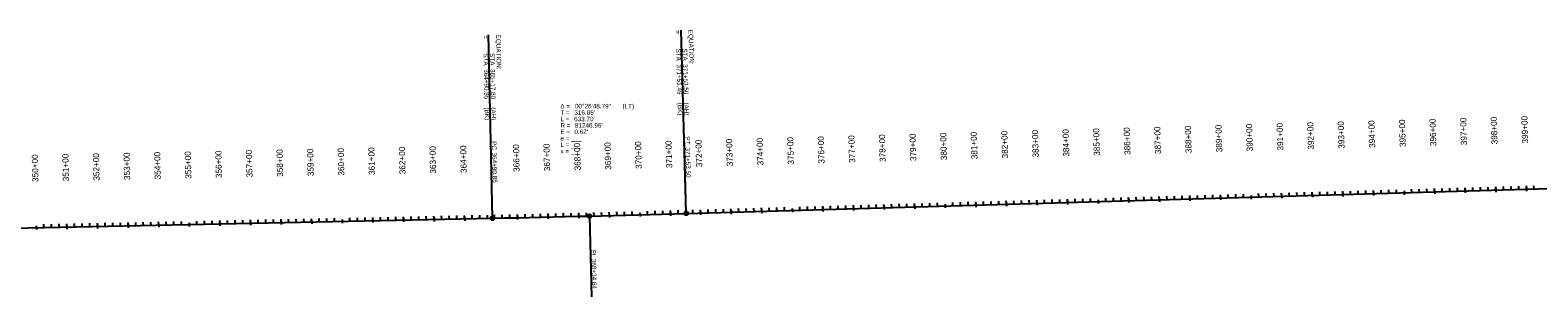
# Model space of a CAD drawing. Extents: x 22693007 to 22771804, y 6223023 to 6251673.
# Drawn here: x 22712700 to 22717627, y 6235361 to 6236234 of the extents above; entities that cross this region are included whole.
import ezdxf

# ---------------------------------------------------------------- set-up
doc = ezdxf.new("R2010")
doc.units = 0
for name, color, linetype in [('Default', 7, 'Continuous'), ('Draft_2', 7, 'Continuous'), ('NamedBoundary', 7, 'Continuous'), ('SheetBorder', 7, 'Continuous'), ('TextAlignment', 7, 'Continuous')]:
    doc.layers.add(name, color=color, linetype=linetype)

msp = doc.modelspace()

# ---------------------------------------------------------------- linework, layer by layer
at = {"layer": 'Default'}
for p, q in [((22714843.8, 6235633.8), (22719408.5, 6235765)), ((22714843.8, 6235633.8), (22719408.5, 6235765)), ((22709036.9, 6235509.8), (22714210.3, 6235618))]:
    msp.add_line(p, q, dxfattribs=at)
msp.add_arc((22712508.9, 6316847.2), 81247, 271.19995, 271.646835, dxfattribs=at)
at = {"layer": 'Draft_2'}
for p, q in [((22716789.5, 6235689.7), (22716789.2, 6235700.6)), ((22716889.5, 6235692.6), (22716889.2, 6235703.5)), ((22716989.4, 6235695.4), (22716989.1, 6235706.4)), ((22717089.4, 6235698.3), (22717089.1, 6235709.2)), ((22717189.2, 6235707.3), (22717189.5, 6235695.1)), ((22717289.3, 6235704.1), (22717289, 6235715)), ((22717389.3, 6235706.9), (22717389, 6235717.9)), ((22717489.2, 6235709.8), (22717488.9, 6235720.7)), ((22717589.2, 6235712.7), (22717588.9, 6235723.6)), ((22714990.3, 6235638), (22714989.9, 6235648.9)), ((22715090.2, 6235640.8), (22715089.9, 6235651.8)), ((22715190, 6235649.8), (22715190.4, 6235637.6)), ((22715290.1, 6235646.6), (22715289.8, 6235657.5)), ((22715390.1, 6235649.5), (22715389.8, 6235660.4)), ((22715490.1, 6235652.3), (22715489.7, 6235663.3)), ((22715590, 6235655.2), (22715589.7, 6235666.1)), ((22715689.8, 6235664.2), (22715690.1, 6235652)), ((22715789.9, 6235661), (22715789.6, 6235671.9)), ((22715889.9, 6235663.8), (22715889.6, 6235674.8)), ((22715989.9, 6235666.7), (22715989.5, 6235677.6)), ((22716089.8, 6235669.6), (22716089.5, 6235680.5)), ((22716189.6, 6235678.6), (22716189.9, 6235666.3)), ((22716289.7, 6235675.3), (22716289.4, 6235686.2)), ((22716389.7, 6235678.2), (22716389.4, 6235689.1)), ((22716489.6, 6235681.1), (22716489.3, 6235692)), ((22716589.6, 6235684), (22716589.3, 6235694.9)), ((22716689.4, 6235692.9), (22716689.7, 6235680.7)), ((22712819.8, 6235588.9), (22712819.6, 6235599.8)), ((22712919.8, 6235591), (22712919.5, 6235601.9)), ((22713019.7, 6235593.1), (22713019.5, 6235604)), ((22713119.7, 6235595.2), (22713119.5, 6235606.1)), ((22713219.6, 6235603.4), (22713219.8, 6235591.2)), ((22713319.7, 6235599.4), (22713319.4, 6235610.3)), ((22713419.7, 6235601.5), (22713419.4, 6235612.4)), ((22713519.6, 6235603.6), (22713519.4, 6235614.5)), ((22713619.6, 6235605.7), (22713619.4, 6235616.6)), ((22713719.5, 6235613.9), (22713719.7, 6235601.6)), ((22713819.6, 6235609.8), (22713819.3, 6235620.8)), ((22713919.5, 6235611.9), (22713919.3, 6235622.9)), ((22714019.5, 6235614), (22714019.3, 6235624.9)), ((22714119.5, 6235616.1), (22714119.3, 6235627)), ((22714292.5, 6235619.8), (22714292.3, 6235630.7)), ((22714392.5, 6235622), (22714392.2, 6235633)), ((22714492.5, 6235624.4), (22714492.2, 6235635.3)), ((22714592.4, 6235626.9), (22714592.1, 6235637.8)), ((22714692.2, 6235635.7), (22714692.6, 6235623.4)), ((22714792.4, 6235632.3), (22714792, 6235643.2)), ((22714890.3, 6235635.1), (22714890, 6235646)), ((22712719.7, 6235593), (22712719.9, 6235580.7))]:
    msp.add_line(p, q, dxfattribs=at)
at = {"layer": 'NamedBoundary'}
for p, q in [((22714843.8, 6235633.8), (22719408.5, 6235765)), ((22709036.9, 6235509.8), (22714210.3, 6235618))]:
    msp.add_line(p, q, dxfattribs=at)
msp.add_arc((22712508.9, 6316847.2), 81247, 271.19995, 271.646835, dxfattribs=at)
at = {"layer": 'SheetBorder'}
for p, q in [((22716714.6, 6235687.5), (22716714.2, 6235698.5)), ((22716739.5, 6235688.3), (22716739.2, 6235699.2)), ((22716764.5, 6235689), (22716764.2, 6235699.9)), ((22716814.5, 6235690.4), (22716814.2, 6235701.3)), ((22716839.5, 6235691.1), (22716839.2, 6235702.1)), ((22716864.5, 6235691.9), (22716864.2, 6235702.8)), ((22716889.3, 6235698.7), (22716889.7, 6235686.5)), ((22716914.5, 6235693.3), (22716914.2, 6235704.2)), ((22716939.5, 6235694), (22716939.1, 6235704.9)), ((22716964.4, 6235694.7), (22716964.1, 6235705.6)), ((22716989.3, 6235701.6), (22716989.6, 6235689.3)), ((22717014.4, 6235696.2), (22717014.1, 6235707.1)), ((22717039.4, 6235696.9), (22717039.1, 6235707.8)), ((22717064.4, 6235697.6), (22717064.1, 6235708.5)), ((22717089.2, 6235704.4), (22717089.6, 6235692.2)), ((22717114.4, 6235699), (22717114.1, 6235710)), ((22717139.4, 6235699.8), (22717139.1, 6235710.7)), ((22717164.4, 6235700.5), (22717164.1, 6235711.4)), ((22717189.2, 6235707.3), (22717189.5, 6235695.1)), ((22717214.3, 6235701.9), (22717214, 6235712.8)), ((22717239.3, 6235702.6), (22717239, 6235713.5)), ((22717264.3, 6235703.4), (22717264, 6235714.3)), ((22717289.1, 6235710.2), (22717289.5, 6235698)), ((22717314.3, 6235704.8), (22717314, 6235715.7)), ((22717339.3, 6235705.5), (22717339, 6235716.4)), ((22717364.3, 6235706.2), (22717364, 6235717.1)), ((22717389.1, 6235713.1), (22717389.4, 6235700.8)), ((22717414.3, 6235707.7), (22717413.9, 6235718.6)), ((22717439.3, 6235708.4), (22717438.9, 6235719.3)), ((22717464.2, 6235709.1), (22717463.9, 6235720)), ((22717489.1, 6235715.9), (22717489.4, 6235703.7)), ((22717514.2, 6235710.5), (22717513.9, 6235721.5)), ((22717539.2, 6235711.3), (22717538.9, 6235722.2)), ((22717564.2, 6235712), (22717563.9, 6235722.9)), ((22717589, 6235718.8), (22717589.4, 6235706.6)), ((22717614.2, 6235713.4), (22717613.9, 6235724.3)), ((22714965.3, 6235637.3), (22714965, 6235648.2)), ((22715015.3, 6235638.7), (22715014.9, 6235649.6)), ((22715040.2, 6235639.4), (22715039.9, 6235650.3)), ((22715065.2, 6235640.1), (22715064.9, 6235651)), ((22715115.2, 6235641.6), (22715114.9, 6235652.5)), ((22715140.2, 6235642.3), (22715139.9, 6235653.2)), ((22715165.2, 6235643), (22715164.9, 6235653.9)), ((22715190, 6235649.8), (22715190.4, 6235637.6)), ((22715215.2, 6235644.4), (22715214.9, 6235655.4)), ((22715240.2, 6235645.2), (22715239.8, 6235656.1)), ((22715265.1, 6235645.9), (22715264.8, 6235656.8)), ((22715290, 6235652.7), (22715290.3, 6235640.5)), ((22715315.1, 6235647.3), (22715314.8, 6235658.2)), ((22715340.1, 6235648), (22715339.8, 6235658.9)), ((22715365.1, 6235648.7), (22715364.8, 6235659.7)), ((22715389.9, 6235655.6), (22715390.3, 6235643.3)), ((22715415.1, 6235650.2), (22715414.8, 6235661.1)), ((22715440.1, 6235650.9), (22715439.8, 6235661.8)), ((22715465.1, 6235651.6), (22715464.8, 6235662.5)), ((22715489.9, 6235658.5), (22715490.2, 6235646.2)), ((22715515, 6235653.1), (22715514.7, 6235664)), ((22715540, 6235653.8), (22715539.7, 6235664.7)), ((22715565, 6235654.5), (22715564.7, 6235665.4)), ((22715589.8, 6235661.3), (22715590.2, 6235649.1)), ((22715615, 6235655.9), (22715614.7, 6235666.8)), ((22715640, 6235656.7), (22715639.7, 6235667.6)), ((22715665, 6235657.4), (22715664.7, 6235668.3)), ((22715689.8, 6235664.2), (22715690.1, 6235652)), ((22715715, 6235658.8), (22715714.6, 6235669.7)), ((22715740, 6235659.5), (22715739.6, 6235670.4)), ((22715764.9, 6235660.2), (22715764.6, 6235671.2)), ((22715789.8, 6235667.1), (22715790.1, 6235654.8)), ((22715814.9, 6235661.7), (22715814.6, 6235672.6)), ((22715839.9, 6235662.4), (22715839.6, 6235673.3)), ((22715864.9, 6235663.1), (22715864.6, 6235674)), ((22715889.7, 6235670), (22715890.1, 6235657.7)), ((22715914.9, 6235664.6), (22715914.6, 6235675.5)), ((22715939.9, 6235665.3), (22715939.6, 6235676.2)), ((22715964.9, 6235666), (22715964.5, 6235676.9)), ((22715989.7, 6235672.8), (22715990, 6235660.6)), ((22716014.8, 6235667.4), (22716014.5, 6235678.3)), ((22716039.8, 6235668.1), (22716039.5, 6235679.1)), ((22716064.8, 6235668.9), (22716064.5, 6235679.8)), ((22716089.6, 6235675.7), (22716090, 6235663.5)), ((22716114.8, 6235670.3), (22716114.5, 6235681.2)), ((22716139.8, 6235671), (22716139.5, 6235681.9)), ((22716164.8, 6235671.7), (22716164.5, 6235682.7)), ((22716189.6, 6235678.6), (22716189.9, 6235666.3)), ((22716214.8, 6235673.2), (22716214.4, 6235684.1)), ((22716239.7, 6235673.9), (22716239.4, 6235684.8)), ((22716264.7, 6235674.6), (22716264.4, 6235685.5)), ((22716289.6, 6235681.4), (22716289.9, 6235669.2)), ((22716314.7, 6235676.1), (22716314.4, 6235687)), ((22716339.7, 6235676.8), (22716339.4, 6235687.7)), ((22716364.7, 6235677.5), (22716364.4, 6235688.4)), ((22716389.5, 6235684.3), (22716389.9, 6235672.1)), ((22716414.7, 6235678.9), (22716414.4, 6235689.8)), ((22716439.7, 6235679.6), (22716439.4, 6235690.6)), ((22716464.7, 6235680.4), (22716464.3, 6235691.3)), ((22716489.5, 6235687.2), (22716489.8, 6235675)), ((22716514.6, 6235681.8), (22716514.3, 6235692.7)), ((22716539.6, 6235682.5), (22716539.3, 6235693.4)), ((22716564.6, 6235683.2), (22716564.3, 6235694.2)), ((22716589.4, 6235690.1), (22716589.8, 6235677.8)), ((22716614.6, 6235684.7), (22716614.3, 6235695.6)), ((22716639.6, 6235685.4), (22716639.3, 6235696.3)), ((22716664.6, 6235686.1), (22716664.3, 6235697)), ((22716689.4, 6235692.9), (22716689.7, 6235680.7)), ((22716789.3, 6235695.8), (22716789.7, 6235683.6)), ((22712769.8, 6235587.9), (22712769.6, 6235598.8)), ((22712794.8, 6235588.4), (22712794.6, 6235599.3)), ((22712844.8, 6235589.4), (22712844.6, 6235600.4)), ((22712869.8, 6235590), (22712869.5, 6235600.9)), ((22712894.8, 6235590.5), (22712894.5, 6235601.4)), ((22712944.8, 6235591.5), (22712944.5, 6235602.5)), ((22712969.8, 6235592.1), (22712969.5, 6235603)), ((22712994.7, 6235592.6), (22712994.5, 6235603.5)), ((22713019.6, 6235599.2), (22713019.9, 6235587)), ((22713044.7, 6235593.6), (22713044.5, 6235604.6)), ((22713069.7, 6235594.2), (22713069.5, 6235605.1)), ((22713094.7, 6235594.7), (22713094.5, 6235605.6)), ((22713119.6, 6235601.3), (22713119.8, 6235589.1)), ((22713144.7, 6235595.7), (22713144.5, 6235606.6)), ((22713169.7, 6235596.2), (22713169.5, 6235607.2)), ((22713194.7, 6235596.8), (22713194.5, 6235607.7)), ((22713219.6, 6235603.4), (22713219.8, 6235591.2)), ((22713244.7, 6235597.8), (22713244.5, 6235608.7)), ((22713269.7, 6235598.3), (22713269.5, 6235609.3)), ((22713294.7, 6235598.9), (22713294.5, 6235609.8)), ((22713319.5, 6235605.5), (22713319.8, 6235593.3)), ((22713344.7, 6235599.9), (22713344.4, 6235610.8)), ((22713369.7, 6235600.4), (22713369.4, 6235611.3)), ((22713394.7, 6235601), (22713394.4, 6235611.9)), ((22713419.5, 6235607.6), (22713419.8, 6235595.4)), ((22713444.6, 6235602), (22713444.4, 6235612.9)), ((22713469.6, 6235602.5), (22713469.4, 6235613.4)), ((22713494.6, 6235603), (22713494.4, 6235614)), ((22713519.5, 6235609.7), (22713519.8, 6235597.5)), ((22713544.6, 6235604.1), (22713544.4, 6235615)), ((22713569.6, 6235604.6), (22713569.4, 6235615.5)), ((22713594.6, 6235605.1), (22713594.4, 6235616.1)), ((22713619.5, 6235611.8), (22713619.7, 6235599.5)), ((22713644.6, 6235606.2), (22713644.4, 6235617.1)), ((22713669.6, 6235606.7), (22713669.4, 6235617.6)), ((22713694.6, 6235607.2), (22713694.4, 6235618.1)), ((22713719.5, 6235613.9), (22713719.7, 6235601.6)), ((22713744.6, 6235608.3), (22713744.4, 6235619.2)), ((22713769.6, 6235608.8), (22713769.3, 6235619.7)), ((22713794.6, 6235609.3), (22713794.3, 6235620.2)), ((22713819.4, 6235616), (22713819.7, 6235603.7)), ((22713844.6, 6235610.4), (22713844.3, 6235621.3)), ((22713869.6, 6235610.9), (22713869.3, 6235621.8)), ((22713894.5, 6235611.4), (22713894.3, 6235622.3)), ((22713919.4, 6235618.1), (22713919.7, 6235605.8)), ((22713944.5, 6235612.5), (22713944.3, 6235623.4)), ((22713969.5, 6235613), (22713969.3, 6235623.9)), ((22713994.5, 6235613.5), (22713994.3, 6235624.4)), ((22714019.4, 6235620.1), (22714019.6, 6235607.9)), ((22714044.5, 6235614.6), (22714044.3, 6235625.5)), ((22714069.5, 6235615.1), (22714069.3, 6235626)), ((22714094.5, 6235615.6), (22714094.3, 6235626.5)), ((22714119.4, 6235622.2), (22714119.6, 6235610)), ((22714144.5, 6235616.6), (22714144.3, 6235627.6)), ((22714169.5, 6235617.2), (22714169.3, 6235628.1)), ((22714194.5, 6235617.7), (22714194.3, 6235628.6)), ((22714217.5, 6235618.2), (22714217.3, 6235629.1)), ((22714242.5, 6235618.7), (22714242.3, 6235629.6)), ((22714267.5, 6235619.2), (22714267.3, 6235630.2)), ((22714292.4, 6235625.9), (22714292.6, 6235613.7)), ((22714317.5, 6235620.3), (22714317.3, 6235631.3)), ((22714342.5, 6235620.9), (22714342.3, 6235631.8)), ((22714367.5, 6235621.5), (22714367.2, 6235632.4)), ((22714392.3, 6235628.2), (22714392.6, 6235615.9)), ((22714417.5, 6235622.6), (22714417.2, 6235633.5)), ((22714442.5, 6235623.2), (22714442.2, 6235634.1)), ((22714467.5, 6235623.8), (22714467.2, 6235634.7)), ((22714492.3, 6235630.5), (22714492.6, 6235618.3)), ((22714517.4, 6235625), (22714517.2, 6235636)), ((22714542.4, 6235625.7), (22714542.2, 6235636.6)), ((22714567.4, 6235626.3), (22714567.2, 6235637.2)), ((22714592.3, 6235633), (22714592.6, 6235620.8)), ((22714617.4, 6235627.6), (22714617.1, 6235638.5)), ((22714642.4, 6235628.2), (22714642.1, 6235639.1)), ((22714667.4, 6235628.9), (22714667.1, 6235639.8)), ((22714692.2, 6235635.7), (22714692.6, 6235623.4)), ((22714717.4, 6235630.2), (22714717.1, 6235641.1)), ((22714742.4, 6235630.9), (22714742.1, 6235641.8)), ((22714767.4, 6235631.6), (22714767.1, 6235642.5)), ((22714792.2, 6235638.4), (22714792.5, 6235626.2)), ((22714817.3, 6235633), (22714817, 6235643.9)), ((22714842.3, 6235633.7), (22714842, 6235644.6)), ((22714865.3, 6235634.4), (22714865, 6235645.3)), ((22714890.1, 6235641.2), (22714890.5, 6235629)), ((22714915.3, 6235635.8), (22714915, 6235646.7)), ((22714940.3, 6235636.5), (22714940, 6235647.4)), ((22714990.1, 6235644.1), (22714990.4, 6235631.9)), ((22715090, 6235647), (22715090.4, 6235634.7)), ((22712719.7, 6235593), (22712719.9, 6235580.7)), ((22712744.8, 6235587.4), (22712744.6, 6235598.3)), ((22712819.7, 6235595), (22712819.9, 6235582.8)), ((22712919.6, 6235597.1), (22712919.9, 6235584.9))]:
    msp.add_line(p, q, dxfattribs=at)
at = {"layer": 'TextAlignment'}
for p, q in [((22714210.3, 6235618), (22714197.8, 6236217.9)), ((22714197.8, 6236217.9), (22714197.8, 6236217.9)), ((22714843.8, 6235633.8), (22714826.6, 6236233.5)), ((22714826.6, 6236233.5), (22714826.6, 6236233.5)), ((22714210.3, 6235618), (22714205, 6235870)), ((22714205, 6235870), (22714205, 6235870)), ((22714843.8, 6235633.8), (22714836.6, 6235885.7)), ((22714836.6, 6235885.7), (22714836.6, 6235885.7)), ((22714527.1, 6235624.7), (22714533.7, 6235360.7)), ((22714533.7, 6235360.7), (22714533.7, 6235360.7))]:
    msp.add_line(p, q, dxfattribs=at)
for centre, radius in [((22714210.3, 6235618), 6.24), ((22714210.3, 6235618), 5.34), ((22714527.1, 6235624.7), 6.24), ((22714843.8, 6235633.8), 6.24), ((22714843.8, 6235633.8), 5.34)]:
    msp.add_circle(centre, radius, dxfattribs=at)

# ---------------------------------------------------------------- texts
at = {"layer": 'Draft_2'}
for s, rotation, p in [('380+00', 91.6468, (22715695.7, 6235808.3)), ('385+00', 91.6468, (22716195.5, 6235822.7)), ('390+00', 91.6468, (22716695.3, 6235837.1)), ('395+00', 91.6468, (22717195.1, 6235851.4)), ('360+00', 91.1986, (22713726.5, 6235757.9)), ('370+00', 91.54, (22714698.4, 6235779.8)), ('375+00', 91.6468, (22715195.9, 6235793.9)), ('350+00', 91.1986, (22712726.7, 6235737)), ('355+00', 91.1986, (22713226.6, 6235747.5))]:
    msp.add_text(s, height=20.04, rotation=rotation, dxfattribs=at).set_placement(p)
at = {"layer": 'SheetBorder'}
for s, rotation, p in [('397+00', 91.6468, (22717395, 6235857.2)), ('398+00', 91.6468, (22717494.9, 6235860)), ('399+00', 91.6468, (22717594.9, 6235862.9)), ('379+00', 91.6468, (22715595.7, 6235805.4)), ('380+00', 91.6468, (22715695.7, 6235808.3)), ('381+00', 91.6468, (22715795.6, 6235811.2)), ('382+00', 91.6468, (22715895.6, 6235814.1)), ('383+00', 91.6468, (22715995.6, 6235816.9)), ('384+00', 91.6468, (22716095.5, 6235819.8)), ('385+00', 91.6468, (22716195.5, 6235822.7)), ('386+00', 91.6468, (22716295.4, 6235825.6)), ('387+00', 91.6468, (22716395.4, 6235828.4)), ('388+00', 91.6468, (22716495.3, 6235831.3)), ('389+00', 91.6468, (22716595.3, 6235834.2)), ('390+00', 91.6468, (22716695.3, 6235837.1)), ('391+00', 91.6468, (22716795.2, 6235839.9)), ('392+00', 91.6468, (22716895.2, 6235842.8)), ('393+00', 91.6468, (22716995.1, 6235845.7)), ('394+00', 91.6468, (22717095.1, 6235848.5)), ('395+00', 91.6468, (22717195.1, 6235851.4)), ('396+00', 91.6468, (22717295, 6235854.3)), ('360+00', 91.1986, (22713726.5, 6235757.9)), ('361+00', 91.1986, (22713826.4, 6235760)), ('362+00', 91.1986, (22713926.4, 6235762.1)), ('363+00', 91.1986, (22714026.4, 6235764.2)), ('364+00', 91.1986, (22714126.4, 6235766.3)), ('366+00', 91.2579, (22714299.2, 6235770)), ('367+00', 91.3284, (22714399, 6235772.2)), ('368+00', 91.399, (22714498.8, 6235774.6)), ('369+00', 91.4695, (22714598.6, 6235777.1)), ('370+00', 91.54, (22714698.4, 6235779.8)), ('371+00', 91.6105, (22714798.2, 6235782.5)), ('372+00', 91.6468, (22714896, 6235785.3)), ('373+00', 91.6468, (22714996, 6235788.2)), ('374+00', 91.6468, (22715095.9, 6235791.1)), ('375+00', 91.6468, (22715195.9, 6235793.9)), ('376+00', 91.6468, (22715295.8, 6235796.8)), ('377+00', 91.6468, (22715395.8, 6235799.7)), ('378+00', 91.6468, (22715495.8, 6235802.6)), ('350+00', 91.1986, (22712726.7, 6235737)), ('351+00', 91.1986, (22712826.7, 6235739.1)), ('352+00', 91.1986, (22712926.6, 6235741.2)), ('353+00', 91.1986, (22713026.6, 6235743.3)), ('354+00', 91.1986, (22713126.6, 6235745.4)), ('355+00', 91.1986, (22713226.6, 6235747.5)), ('356+00', 91.1986, (22713326.6, 6235749.6)), ('357+00', 91.1986, (22713426.5, 6235751.7)), ('358+00', 91.1986, (22713526.5, 6235753.7)), ('359+00', 91.1986, (22713626.5, 6235755.8))]:
    msp.add_text(s, height=20.04, rotation=rotation, dxfattribs=at).set_placement(p)
at = {"layer": 'TextAlignment'}
for s, rotation, p in [('=', 271.2, (22714180.1, 6236217.5)), ('EQUATION:', 271.2, (22714222.1, 6236218.4)), ('=', 271.6468, (22714808.9, 6236233)), ('EQUATION:', 271.6468, (22714850.9, 6236234.2)), ('STA ', 271.2, (22714181.3, 6236157.5)), ('STA ', 271.2, (22714202.3, 6236158)), ('STA ', 271.6468, (22714810.6, 6236173)), ('STA ', 271.6468, (22714831.6, 6236173.6)), ('364+90.85', 271.2, (22714182.4, 6236105.6)), ('365+17.80', 271.2, (22714203.4, 6236106)), ('371+51.49', 271.6468, (22714812.1, 6236121.1)), ('371+53.50', 271.6468, (22714833.1, 6236121.7)), ('(BK)', 271.6468, (22714815.7, 6235995.8)), ('(AH)', 271.6468, (22714836.7, 6235996.4)), ('(BK)', 271.2, (22714185.1, 6235980.3)), ('(AH)', 271.2, (22714206, 6235980.7)), ('PC', 271.1999, (22714208.3, 6235870)), ('PT', 271.6468, (22714839.9, 6235885.8)), ('371+53.50', 271.6468, (22714840.9, 6235849.5)), ('364+90.85', 271.1999, (22714209.1, 6235832.7)), ('PI ', 271.4234, (22714533.1, 6235515)), ('368+34.64', 271.4234, (22714533.9, 6235485.1))]:
    msp.add_text(s, height=15, rotation=rotation, dxfattribs=at).set_placement(p)
for s, p in [(' (LT)', (22714629.7, 6235977.3)), ('T = ', (22714432.5, 6235956.3)), ('Δ = ', (22714432.5, 6235977.3)), ('L = ', (22714432.5, 6235935.3)), ("633.70'", (22714477.2, 6235935.3)), ("316.85'", (22714478.1, 6235956.3)), ('00°26\'48.79"', (22714480, 6235977.3)), ('R = ', (22714432.5, 6235914.3)), ('E = ', (22714432.5, 6235893.3)), ("0.62'", (22714478.1, 6235893.3)), ("81246.96'", (22714479.9, 6235914.3)), ('e = ___ ', (22714432.5, 6235872.3)), ('L = ___', (22714432.5, 6235851.3)), ('x = ___', (22714432.5, 6235830.3))]:
    msp.add_text(s, height=15, dxfattribs=at).set_placement(p)

doc.saveas('drawing.dxf')
